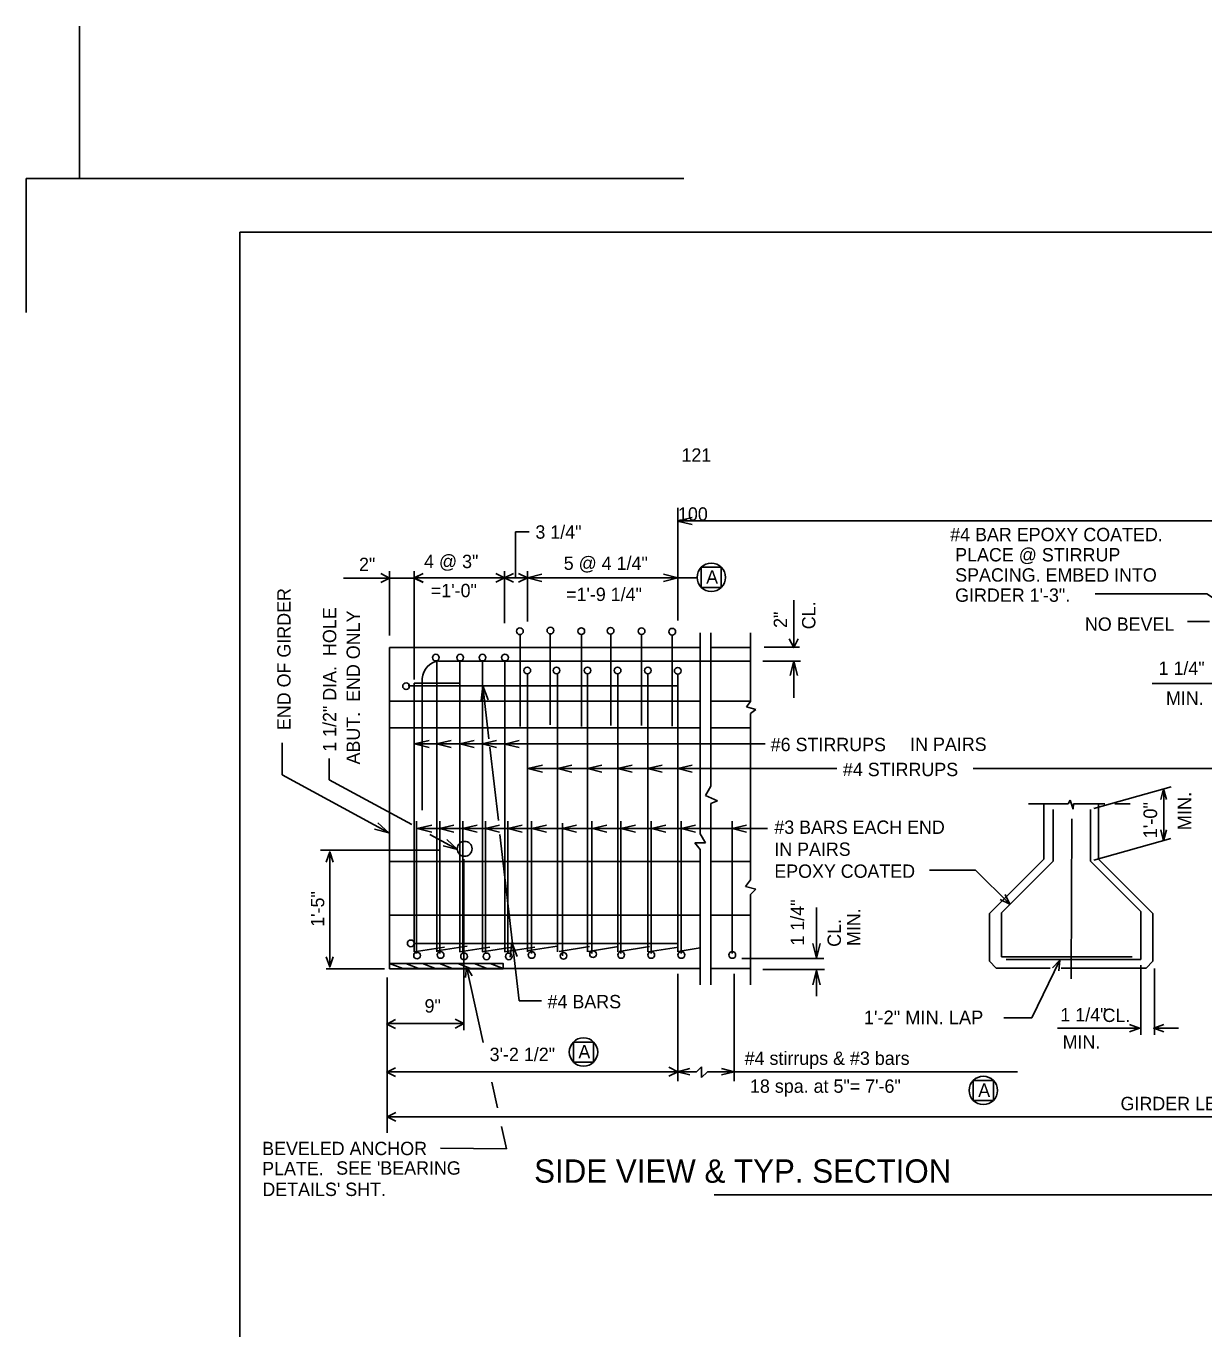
# Model space of a CAD drawing. Extents: x 1005.3 to 1101.9, y 2006.8 to 2073.3.
# Drawn here: x 1008.52 to 1037.89, y 2040.81 to 2073.29 of the extents above; entities that cross this region are included whole.
import ezdxf

# ---------------------------------------------------------------- set-up
doc = ezdxf.new("R2010")
doc.units = 0
for name, color, linetype in [('Level 1', 7, 'Continuous'), ('Level 2', 7, 'Continuous'), ('Level 5', 7, 'Continuous'), ('Level 6', 7, 'Continuous'), ('Level 60', 7, 'Continuous')]:
    doc.layers.add(name, color=color, linetype=linetype)

msp = doc.modelspace()

# ---------------------------------------------------------------- linework, layer by layer
at = {"layer": 'Level 1'}
for p, q in [((1024.919, 2069.489), (1008.518, 2069.489)), ((1008.518, 2069.489), (1008.518, 2066.149)), ((1013.852, 2012.158), (1013.852, 2068.156)), ((1097.517, 2068.156), (1013.852, 2068.156))]:
    msp.add_line(p, q, dxfattribs=at)
at = {"layer": 'Level 2'}
for p, q in [((1009.852, 2069.489), (1009.852, 2073.293)), ((1024.77, 2060.812), (1024.77, 2061.278)), ((1024.765, 2060.951), (1025.125, 2061.041)), ((1024.765, 2060.951), (1025.125, 2060.861)), ((1024.771, 2058.471), (1024.771, 2060.959)), ((1024.772, 2060.959), (1050.923, 2060.959)), ((1020.725, 2059.534), (1020.725, 2060.679)), ((1020.725, 2060.679), (1021.066, 2060.679)), ((1017.583, 2058.096), (1017.583, 2059.701)), ((1018.196, 2057.002), (1018.196, 2059.701)), ((1020.452, 2058.408), (1020.452, 2059.701)), ((1021.021, 2058.45), (1021.021, 2059.701)), ((1025.855, 2059.797), (1025.355, 2059.797)), ((1025.355, 2059.797), (1025.355, 2059.297)), ((1025.855, 2059.297), (1025.855, 2059.797)), ((1018.196, 2059.528), (1016.436, 2059.528)), ((1021.021, 2059.534), (1018.196, 2059.534)), ((1021.021, 2059.534), (1021.381, 2059.624)), ((1021.021, 2059.534), (1025.246, 2059.534)), ((1021.021, 2059.534), (1021.381, 2059.444)), ((1024.771, 2059.534), (1024.411, 2059.624)), ((1024.771, 2059.534), (1024.411, 2059.624)), ((1024.771, 2059.534), (1024.411, 2059.444)), ((1024.771, 2059.534), (1024.411, 2059.444)), ((1025.355, 2059.297), (1025.855, 2059.297)), ((1025.36, 2059.297), (1025.36, 2059.297)), ((1027.661, 2057.795), (1027.661, 2058.977)), ((1038.024, 2058.448), (1037.478, 2058.448)), ((1020.836, 2058.112), (1020.836, 2055.824)), ((1021.585, 2058.136), (1021.585, 2055.872)), ((1022.367, 2058.12), (1022.367, 2055.824)), ((1023.1, 2058.12), (1023.1, 2055.856)), ((1023.865, 2058.12), (1023.865, 2055.856)), ((1024.63, 2058.104), (1024.63, 2055.84)), ((1025.329, 2053.154), (1025.329, 2058.16)), ((1025.593, 2058.16), (1025.593, 2054.339)), ((1026.586, 2058.16), (1026.586, 2056.448)), ((1017.583, 2049.915), (1017.583, 2057.795)), ((1025.329, 2057.795), (1017.583, 2057.795)), ((1026.586, 2057.795), (1025.593, 2057.795)), ((1026.926, 2057.805), (1027.804, 2057.805)), ((1018.76, 2057.461), (1018.76, 2051.385)), ((1026.586, 2057.461), (1018.806, 2057.461)), ((1019.338, 2057.461), (1019.338, 2050.206)), ((1019.897, 2057.461), (1019.897, 2050.206)), ((1020.457, 2057.461), (1020.457, 2050.206)), ((1026.89, 2057.461), (1027.828, 2057.461)), ((1027.661, 2057.461), (1027.571, 2057.101)), ((1027.661, 2056.545), (1027.661, 2057.461)), ((1027.661, 2057.461), (1027.751, 2057.101)), ((1021.021, 2057.131), (1021.021, 2050.206)), ((1021.771, 2057.139), (1021.771, 2050.206)), ((1022.521, 2057.155), (1022.521, 2050.206)), ((1023.271, 2057.147), (1023.271, 2050.206)), ((1024.021, 2057.139), (1024.021, 2050.206)), ((1024.771, 2057.131), (1024.771, 2050.206)), ((1018.043, 2056.838), (1024.771, 2056.838)), ((1018.196, 2056.481), (1018.196, 2056.909)), ((1018.196, 2056.905), (1019.326, 2056.905)), ((1018.196, 2056.905), (1018.196, 2050.206)), ((1018.399, 2057.026), (1018.399, 2053.739)), ((1019.338, 2056.808), (1019.338, 2056.969)), ((1019.911, 2056.838), (1019.863, 2056.47)), ((1019.897, 2056.808), (1019.897, 2056.969)), ((1019.911, 2056.838), (1020.042, 2056.491)), ((1020.062, 2055.523), (1019.911, 2056.838)), ((1020.457, 2056.808), (1020.457, 2056.969)), ((1039.42, 2056.897), (1036.598, 2056.897)), ((1025.329, 2056.461), (1017.583, 2056.461)), ((1026.586, 2056.461), (1025.593, 2056.461)), ((1026.586, 2056.448), (1026.487, 2056.316)), ((1037.712, 2056.58), (1037.712, 2056.58)), ((1026.487, 2056.316), (1026.718, 2056.25)), ((1026.718, 2056.25), (1026.586, 2056.151)), ((1026.586, 2056.151), (1026.586, 2052.002)), ((1025.329, 2055.794), (1017.583, 2055.794)), ((1026.586, 2055.794), (1025.593, 2055.794)), ((1014.904, 2054.622), (1014.904, 2055.42)), ((1018.206, 2055.392), (1018.566, 2055.482)), ((1018.755, 2055.392), (1019.115, 2055.482)), ((1019.335, 2055.392), (1019.695, 2055.482)), ((1019.891, 2055.392), (1020.251, 2055.482)), ((1020.454, 2055.391), (1020.814, 2055.481)), ((1018.206, 2055.392), (1018.91, 2055.392)), ((1018.206, 2055.392), (1018.566, 2055.302)), ((1018.755, 2055.392), (1019.115, 2055.302)), ((1018.91, 2055.392), (1019.613, 2055.392)), ((1019.335, 2055.392), (1019.695, 2055.302)), ((1019.613, 2055.392), (1026.945, 2055.392)), ((1019.891, 2055.392), (1020.251, 2055.302)), ((1020.086, 2055.314), (1020.297, 2053.481)), ((1020.454, 2055.391), (1020.814, 2055.301)), ((1021.032, 2054.777), (1021.392, 2054.867)), ((1021.032, 2054.777), (1021.769, 2054.777)), ((1021.032, 2054.777), (1021.392, 2054.687)), ((1021.769, 2054.777), (1022.129, 2054.867)), ((1021.769, 2054.777), (1022.54, 2054.777)), ((1021.769, 2054.777), (1022.129, 2054.687)), ((1022.518, 2054.777), (1022.878, 2054.867)), ((1022.518, 2054.777), (1022.878, 2054.687)), ((1022.54, 2054.777), (1023.299, 2054.777)), ((1023.269, 2054.777), (1023.629, 2054.867)), ((1023.269, 2054.777), (1023.629, 2054.687)), ((1023.299, 2054.777), (1024.036, 2054.777)), ((1024.016, 2054.777), (1024.376, 2054.867)), ((1024.016, 2054.777), (1024.376, 2054.687)), ((1024.036, 2054.777), (1024.784, 2054.777)), ((1024.769, 2054.777), (1025.129, 2054.867)), ((1024.769, 2054.777), (1025.129, 2054.687)), ((1024.784, 2054.777), (1028.735, 2054.777)), ((1039.747, 2054.777), (1032.138, 2054.777)), ((1014.904, 2054.622), (1017.583, 2053.169)), ((1025.593, 2054.339), (1025.461, 2054.11)), ((1035.141, 2053.782), (1037.069, 2054.325)), ((1036.884, 2054.276), (1036.816, 2054.004)), ((1036.884, 2054.276), (1036.952, 2054.004)), ((1036.887, 2054.284), (1036.887, 2053)), ((1025.461, 2054.11), (1025.757, 2053.978)), ((1025.757, 2053.978), (1025.593, 2053.912)), ((1025.593, 2053.912), (1025.593, 2049.39)), ((1033.515, 2053.902), (1034.5, 2053.902)), ((1033.9, 2052.521), (1033.9, 2053.902)), ((1034.5, 2053.902), (1034.552, 2053.991)), ((1034.552, 2053.991), (1034.629, 2053.764)), ((1034.629, 2053.764), (1034.639, 2053.902)), ((1034.639, 2053.902), (1035.416, 2053.902)), ((1035.257, 2052.521), (1035.257, 2053.902)), ((1035.664, 2053.902), (1036.053, 2053.902)), ((1018.251, 2053.471), (1018.251, 2050.165)), ((1018.839, 2053.471), (1018.839, 2050.165)), ((1019.412, 2053.471), (1019.412, 2050.165)), ((1019.971, 2053.471), (1019.971, 2050.165)), ((1020.531, 2053.471), (1020.531, 2050.165)), ((1021.121, 2053.471), (1021.121, 2050.165)), ((1022.629, 2053.471), (1022.629, 2050.165)), ((1023.353, 2053.471), (1023.353, 2050.165)), ((1024.103, 2053.471), (1024.103, 2050.165)), ((1024.853, 2053.471), (1024.853, 2050.165)), ((1026.124, 2053.471), (1026.124, 2050.165)), ((1034.129, 2052.474), (1034.129, 2053.762)), ((1034.579, 2049.537), (1034.594, 2053.522)), ((1035.058, 2052.474), (1035.058, 2053.762)), ((1017.566, 2053.179), (1017.206, 2053.272)), ((1017.566, 2053.179), (1017.292, 2053.43)), ((1018.273, 2053.281), (1018.633, 2053.371)), ((1018.273, 2053.281), (1018.988, 2053.281)), ((1018.273, 2053.281), (1018.633, 2053.191)), ((1018.828, 2053.281), (1019.188, 2053.371)), ((1018.828, 2053.281), (1019.188, 2053.191)), ((1018.988, 2053.281), (1019.691, 2053.281)), ((1019.403, 2053.281), (1019.763, 2053.371)), ((1019.403, 2053.281), (1019.763, 2053.191)), ((1019.691, 2053.281), (1021.132, 2053.281)), ((1019.967, 2053.281), (1020.327, 2053.371)), ((1019.967, 2053.281), (1020.327, 2053.191)), ((1020.529, 2053.281), (1020.889, 2053.371)), ((1020.529, 2053.281), (1020.889, 2053.191)), ((1021.132, 2053.281), (1021.492, 2053.371)), ((1021.132, 2053.281), (1022.64, 2053.281)), ((1021.132, 2053.281), (1021.492, 2053.191)), ((1021.886, 2053.281), (1022.246, 2053.371)), ((1021.886, 2053.281), (1022.246, 2053.191)), ((1021.895, 2053.419), (1021.895, 2050.113)), ((1022.64, 2053.281), (1023, 2053.371)), ((1022.64, 2053.281), (1024.114, 2053.281)), ((1022.64, 2053.281), (1023, 2053.191)), ((1023.353, 2053.281), (1023.713, 2053.371)), ((1023.353, 2053.281), (1023.713, 2053.191)), ((1024.114, 2053.281), (1024.474, 2053.371)), ((1024.114, 2053.281), (1027.008, 2053.281)), ((1024.114, 2053.281), (1024.474, 2053.191)), ((1024.853, 2053.281), (1025.213, 2053.371)), ((1024.853, 2053.281), (1025.213, 2053.191)), ((1025.461, 2052.924), (1025.329, 2053.154)), ((1026.124, 2053.281), (1026.484, 2053.371)), ((1026.124, 2053.281), (1026.484, 2053.191)), ((1036.884, 2052.978), (1036.816, 2053.25)), ((1036.884, 2052.978), (1036.952, 2053.25)), ((1020.813, 2048.987), (1020.336, 2053.139)), ((1025.329, 2052.759), (1025.197, 2052.924)), ((1025.197, 2052.924), (1025.461, 2052.924)), ((1035.14, 2052.496), (1037.068, 2053.039)), ((1025.329, 2049.39), (1025.329, 2052.759)), ((1032.542, 2051.163), (1033.9, 2052.521)), ((1036.615, 2051.163), (1035.257, 2052.521)), ((1025.329, 2052.46), (1017.583, 2052.46)), ((1026.586, 2052.46), (1025.593, 2052.46)), ((1032.196, 2052.25), (1031.047, 2052.25)), ((1033.051, 2051.395), (1032.196, 2052.25)), ((1032.841, 2051.186), (1034.129, 2052.474)), ((1036.316, 2051.216), (1035.058, 2052.474)), ((1026.586, 2052.002), (1026.454, 2051.837)), ((1026.454, 2051.837), (1026.718, 2051.771)), ((1026.718, 2051.771), (1026.586, 2051.639)), ((1026.586, 2051.639), (1026.586, 2049.39)), ((1018.76, 2051.385), (1018.76, 2050.206)), ((1028.226, 2050.055), (1028.226, 2051.312)), ((1036.316, 2050.015), (1036.316, 2051.216)), ((1025.329, 2051.127), (1017.583, 2051.127)), ((1026.586, 2051.127), (1025.593, 2051.127)), ((1032.542, 2049.974), (1032.542, 2051.163)), ((1032.841, 2050.084), (1032.841, 2051.186)), ((1036.615, 2049.974), (1036.615, 2051.163)), ((1018.196, 2050.421), (1024.771, 2050.421)), ((1018.196, 2050.206), (1018.949, 2050.327)), ((1018.76, 2050.233), (1019.514, 2050.354)), ((1019.329, 2050.206), (1020.082, 2050.327)), ((1019.888, 2050.206), (1020.642, 2050.327)), ((1020.448, 2050.206), (1021.201, 2050.327)), ((1020.635, 2050.445), (1020.587, 2050.077)), ((1020.635, 2050.445), (1020.765, 2050.097)), ((1021.008, 2050.233), (1021.761, 2050.354)), ((1021.815, 2050.219), (1022.568, 2050.34)), ((1022.541, 2050.219), (1023.295, 2050.34)), ((1023.308, 2050.219), (1024.062, 2050.34)), ((1024.035, 2050.206), (1024.788, 2050.327)), ((1024.775, 2050.219), (1025.329, 2050.308)), ((1028.226, 2050.055), (1028.136, 2050.415)), ((1028.226, 2050.055), (1028.316, 2050.415)), ((1017.583, 2049.915), (1017.913, 2049.792)), ((1026.365, 2050.047), (1028.412, 2050.047)), ((1032.711, 2049.802), (1032.542, 2049.974)), ((1034.58, 2050.084), (1032.841, 2050.084)), ((1032.958, 2050.015), (1036.316, 2050.015)), ((1034.3, 2050.003), (1033.601, 2048.561)), ((1034.577, 2050.084), (1036.103, 2050.084)), ((1036.446, 2049.802), (1036.615, 2049.974)), ((1017.913, 2049.792), (1025.329, 2049.792)), ((1024.771, 2046.987), (1024.771, 2049.659)), ((1025.593, 2049.792), (1026.586, 2049.792)), ((1026.172, 2049.659), (1026.172, 2046.987)), ((1026.887, 2049.771), (1028.426, 2049.771)), ((1028.226, 2049.745), (1028.136, 2049.385)), ((1028.226, 2049.101), (1028.226, 2049.771)), ((1028.226, 2049.745), (1028.316, 2049.385)), ((1034.057, 2049.802), (1032.711, 2049.802)), ((1034.579, 2049.802), (1034.328, 2049.802)), ((1034.579, 2049.802), (1034.579, 2049.802)), ((1034.579, 2049.802), (1034.579, 2049.802)), ((1034.579, 2049.802), (1034.579, 2049.802)), ((1034.579, 2049.802), (1034.579, 2049.802)), ((1034.579, 2049.802), (1034.579, 2049.802)), ((1034.579, 2049.802), (1036.446, 2049.802)), ((1034.579, 2049.802), (1034.579, 2049.802)), ((1034.579, 2049.802), (1034.579, 2049.802)), ((1034.579, 2049.802), (1034.579, 2049.802)), ((1036.315, 2049.876), (1036.315, 2048.14)), ((1036.654, 2049.798), (1036.654, 2048.14)), ((1017.519, 2049.568), (1017.519, 2045.693)), ((1020.813, 2048.987), (1021.369, 2048.987)), ((1033.601, 2048.561), (1032.903, 2048.561)), ((1036.286, 2048.306), (1034.238, 2048.306)), ((1037.252, 2048.306), (1036.639, 2048.306)), ((1022.669, 2047.961), (1022.169, 2047.961)), ((1022.169, 2047.961), (1022.169, 2047.461)), ((1022.669, 2047.461), (1022.669, 2047.961)), ((1022.169, 2047.461), (1022.669, 2047.461)), ((1022.173, 2047.461), (1022.173, 2047.461)), ((1025.239, 2047.221), (1025.363, 2047.344)), ((1025.363, 2047.344), (1025.363, 2047.073)), ((1017.527, 2047.221), (1024.764, 2047.221)), ((1024.764, 2047.221), (1025.239, 2047.221)), ((1025.363, 2047.073), (1025.511, 2047.221)), ((1025.511, 2047.221), (1033.243, 2047.221)), ((1032.639, 2047.004), (1032.139, 2047.004)), ((1032.139, 2047.004), (1032.139, 2046.504)), ((1032.639, 2046.504), (1032.639, 2047.004)), ((1032.139, 2046.504), (1032.639, 2046.504)), ((1032.144, 2046.504), (1032.144, 2046.504)), ((1017.519, 2046.095), (1056.542, 2046.095)), ((1025.674, 2044.148), (1042.378, 2044.148))]:
    msp.add_line(p, q, dxfattribs=at)
for points in [[(1017.361, 2059.419), (1017.583, 2059.53), (1017.361, 2059.641)], [(1018.418, 2059.423), (1018.196, 2059.534), (1018.418, 2059.645)], [(1018.418, 2059.419), (1018.196, 2059.53), (1018.418, 2059.641)], [(1020.23, 2059.423), (1020.452, 2059.534), (1020.23, 2059.645)], [(1020.675, 2059.423), (1020.452, 2059.534), (1020.675, 2059.645)], [(1020.799, 2059.423), (1021.021, 2059.534), (1020.799, 2059.645)], [(1024.766, 2059.531), (1024.771, 2059.534), (1024.766, 2059.537)], [(1039.799, 2057.948), (1037.964, 2059.132), (1035.18, 2059.132)], [(1027.55, 2058.017), (1027.661, 2057.795), (1027.772, 2058.017)], [(1032.933, 2051.637), (1033.051, 2051.395), (1032.809, 2051.513)], [(1034.111, 2049.813), (1034.3, 2050.003), (1034.269, 2049.736)], [(1036.032, 2048.394), (1036.286, 2048.306), (1036.032, 2048.219)], [(1036.893, 2048.219), (1036.639, 2048.306), (1036.893, 2048.394)], [(1017.734, 2047.099), (1017.512, 2047.21), (1017.734, 2047.321)], [(1024.549, 2047.109), (1024.771, 2047.221), (1024.549, 2047.332)], [(1025.073, 2047.299), (1024.764, 2047.221), (1025.073, 2047.142)], [(1025.863, 2047.299), (1026.172, 2047.221), (1025.863, 2047.142)], [(1017.741, 2045.984), (1017.519, 2046.095), (1017.741, 2046.206)]]:
    msp.add_lwpolyline(points, dxfattribs=at)
for centre, radius in [((1025.605, 2059.547), 0.354), ((1020.834, 2058.202), 0.0833), ((1021.593, 2058.219), 0.0833), ((1022.364, 2058.205), 0.0833), ((1023.094, 2058.215), 0.0833), ((1023.867, 2058.203), 0.0833), ((1024.632, 2058.192), 0.0833), ((1018.735, 2057.545), 0.0833), ((1019.342, 2057.545), 0.0833), ((1019.902, 2057.545), 0.0833), ((1020.461, 2057.545), 0.0833), ((1021.017, 2057.226), 0.0833), ((1021.746, 2057.226), 0.0833), ((1022.519, 2057.226), 0.0833), ((1023.269, 2057.226), 0.0833), ((1024.024, 2057.226), 0.0833), ((1024.768, 2057.218), 0.0833), ((1017.994, 2056.832), 0.0833), ((1018.11, 2050.421), 0.0833), ((1022.656, 2050.153), 0.0833), ((1018.267, 2050.12), 0.0833), ((1018.855, 2050.131), 0.0833), ((1019.439, 2050.097), 0.0833), ((1019.998, 2050.097), 0.0833), ((1020.558, 2050.097), 0.0833), ((1021.126, 2050.131), 0.0833), ((1021.921, 2050.11), 0.0833), ((1023.358, 2050.131), 0.0833), ((1024.108, 2050.131), 0.0833), ((1024.858, 2050.131), 0.0833), ((1026.129, 2050.131), 0.0833), ((1022.419, 2047.711), 0.354), ((1032.389, 2046.754), 0.354)]:
    msp.add_circle(centre, radius, dxfattribs=at)
msp.add_arc((1018.865, 2056.998), 0.467, 96.657, 177.0425, dxfattribs=at)
at = {"layer": 'Level 5'}
for p, q in [((1016.076, 2054.497), (1016.076, 2055.029)), ((1018.136, 2053.381), (1016.076, 2054.497)), ((1019.28, 2052.76), (1018.587, 2053.136)), ((1019.28, 2052.76), (1018.921, 2052.852)), ((1019.28, 2052.76), (1019.007, 2053.011)), ((1018.819, 2052.744), (1015.861, 2052.744)), ((1016.09, 2049.832), (1016.09, 2052.699)), ((1019.437, 2052.522), (1019.437, 2048.253)), ((1017.454, 2049.787), (1015.998, 2049.787)), ((1019.437, 2048.419), (1017.527, 2048.419))]:
    msp.add_line(p, q, dxfattribs=at)
for points in [[(1016.002, 2052.445), (1016.09, 2052.699), (1016.177, 2052.445)], [(1016.177, 2050.086), (1016.09, 2049.832), (1016.002, 2050.086)], [(1017.734, 2048.52), (1017.512, 2048.409), (1017.734, 2048.298)], [(1019.215, 2048.531), (1019.437, 2048.419), (1019.215, 2048.308)]]:
    msp.add_lwpolyline(points, dxfattribs=at)
msp.add_circle((1019.455, 2052.778), 0.186, dxfattribs=at)
at = {"layer": 'Level 6'}
for p, q in [((1017.985, 2049.915), (1018.325, 2049.788)), ((1018.403, 2049.915), (1018.743, 2049.788)), ((1018.83, 2049.915), (1019.17, 2049.788)), ((1019.289, 2049.915), (1019.629, 2049.788)), ((1019.696, 2049.915), (1020.036, 2049.788)), ((1020.091, 2049.915), (1020.417, 2049.793)), ((1019.505, 2049.838), (1019.917, 2047.951)), ((1020.133, 2046.963), (1020.274, 2046.32)), ((1020.497, 2045.3), (1020.375, 2045.857)), ((1020.497, 2045.3), (1018.851, 2045.312))]:
    msp.add_line(p, q, dxfattribs=at)
msp.add_lwpolyline([(1017.583, 2049.915), (1020.417, 2049.915), (1020.417, 2049.788), (1017.583, 2049.788)], close=True, dxfattribs=at)
msp.add_lwpolyline([(1019.474, 2049.571), (1019.505, 2049.838), (1019.645, 2049.609)], dxfattribs=at)

# ---------------------------------------------------------------- texts
at = {"layer": 'Level 2'}
for s, height, p in [('3 1/4"', 0.3333, (1021.219, 2060.511)), ('#4 BAR EPOXY COATED. ', 0.33333, (1031.562, 2060.448)), (' PLACE @ STIRRUP', 0.33333, (1031.562, 2059.944)), ('2"', 0.3333, (1016.821, 2059.703)), ('4 @ 3" ', 0.3333, (1018.443, 2059.777)), ('5 @ 4 1/4"', 0.3333, (1021.925, 2059.733)), ('A', 0.333, (1025.477, 2059.387)), (' SPACING. EMBED INTO ', 0.33333, (1031.562, 2059.44)), ('=1\'-0"', 0.3333, (1018.612, 2059.052)), ('=1\'-9 1/4"', 0.3333, (1021.984, 2058.957)), (' GIRDER 1\'-3".', 0.33333, (1031.562, 2058.937)), ('NO BEVEL', 0.3333, (1034.922, 2058.214)), ('1 1/4"', 0.3333, (1036.758, 2057.114)), ('MIN.', 0.3333, (1036.942, 2056.368)), ('#6 STIRRUPS', 0.33333, (1027.087, 2055.213)), ('IN PAIRS', 0.3333, (1030.564, 2055.22)), ('#4 STIRRUPS', 0.33333, (1028.887, 2054.59)), ('#3 BARS EACH END', 0.33244, (1027.178, 2053.151)), ('IN PAIRS', 0.3324, (1027.178, 2052.603)), ('EPOXY COATED', 0.33244, (1027.178, 2052.055)), ('#4 BARS', 0.3333, (1021.522, 2048.801)), ('1\'-2" MIN. LAP', 0.34, (1029.41, 2048.404)), ('1 1/4"', 0.3333, (1034.31, 2048.474)), ('CL.', 0.3333, (1035.361, 2048.46)), ('MIN.', 0.3333, (1034.365, 2047.798)), ('3\'-2 1/2"', 0.3333, (1020.078, 2047.486)), ('A', 0.333, (1022.291, 2047.551)), ('#4 stirrups & #3 bars', 0.33333, (1026.437, 2047.39)), ('18 spa. at 5"= 7\'-6"', 0.33333, (1026.57, 2046.695)), ('A', 0.333, (1032.261, 2046.594)), ('GIRDER LENGTH =  "L"', 0.33333, (1035.81, 2046.261)), ('             SIDE VIEW & TYP. SECTION', 0.58333, (1018.37, 2044.452))]:
    msp.add_text(s, height=height, dxfattribs=at).set_placement(p)
for s, height, p in [('END OF GIRDER', 0.33333, (1015.115, 2055.738)), ('2"', 0.3333, (1027.495, 2058.286)), ('CL.', 0.3333, (1028.201, 2058.253)), ('MIN.', 0.34, (1037.573, 2053.241)), ('1\'-0"', 0.34, (1036.722, 2053.039)), ('1 1/4"', 0.3333, (1027.919, 2050.366)), ('MIN.', 0.3333, (1029.322, 2050.355)), ('CL.', 0.3333, (1028.837, 2050.334))]:
    msp.add_text(s, height=height, rotation=90, dxfattribs=at).set_placement(p)
at = {"layer": 'Level 5'}
for s, height, p in [('1 1/2" DIA.  HOLE', 0.33333, (1016.254, 2055.197)), ('ABUT.  END ONLY', 0.33333, (1016.844, 2054.881)), ('1\'-5"', 0.3333, (1015.953, 2050.833))]:
    msp.add_text(s, height=height, rotation=90, dxfattribs=at).set_placement(p)
msp.add_text('9"', height=0.3333, dxfattribs=at).set_placement((1018.455, 2048.695))
at = {"layer": 'Level 6'}
for s, height, p in [('BEVELED ANCHOR', 0.33333, (1014.405, 2045.14)), ('PLATE.', 0.3333, (1014.405, 2044.64)), ("SEE 'BEARING", 0.33333, (1016.251, 2044.653)), ("DETAILS' SHT.", 0.33333, (1014.411, 2044.121))]:
    msp.add_text(s, height=height, dxfattribs=at).set_placement(p)
at = {"layer": 'Level 60'}
for s, p in [('121', (1024.861, 2062.43)), ('100', (1024.774, 2060.96))]:
    msp.add_text(s, height=0.3333, dxfattribs=at).set_placement(p)

doc.saveas('drawing.dxf')
